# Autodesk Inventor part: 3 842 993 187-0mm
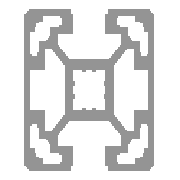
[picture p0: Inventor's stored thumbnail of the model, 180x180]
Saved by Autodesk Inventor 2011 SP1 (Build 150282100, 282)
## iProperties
Category: End -/-
Created: 2011-02
Part Number: 3 842 993 187-0mm
Document SubType Name: Modeling
Designer: SRW
Density: 2.71 g/cm^3
Categories: <MemberInstance><Categories><Category DisplayName="Structural Shapes" InternalName="089c4875-fa83-4c05-b084-43b9cc11f5ed" Mnemonic="GRDR"><CategoryParameter Dis
Stock Number: 3 842 993 187
Description: PROFILE 40x40 2S, -/-
Material: Aluminum-6061
Mass: 40.3687 g
Surface Area: 148.352 cm^2
Volume: 14.8962 cm^3
G_L: 25.000 mm
Author: SRW
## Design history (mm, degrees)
node "Blocks"
  sketch "40x40 2S"
    geometry: L1 (67.598, 49.273)-(67.598, 50.273); L2 (63.848, 46.523)-(64.848, 46.523); L3 (63.848, 44.273)-(63.848, 46.523); L4 (69.848, 53.273)-(64.848, 53.273); L5 (64.848, 53.273)-(64.848, 52.023); L6 (62.098, 49.273)-(60.848, 49.273); L7 (60.848, 49.273)-(60.848, 44.273); L8 (65.348, 39.773)-(60.848, 39.773); L9 (60.848, 39.773)-(60.848, 29.773); L10 (96.348, 54.773)-(85.148, 54.773); L11 (85.148, 53.273)-(84.348, 53.273); L12 (85.148, 54.773)-(85.148, 53.273); L13 (93.848, 53.273)-(88.848, 53.273); L14 (88.848, 50.273)-(91.098, 50.273); L15 (97.848, 49.273)-(96.598, 49.273); L16 (91.098, 50.273)-(91.098, 49.273); L17 (84.348, 53.273)-(84.348, 48.773); L18 (93.848, 46.523)-(94.848, 46.523); L19 (93.348, 45.023)-(91.012, 45.023); L20 (94.848, 46.523)-(94.848, 44.273); L21 (97.848, 44.273)-(97.848, 49.273); L22 (93.348, 39.773)-(93.348, 45.023); L23 (97.848, 39.773)-(93.348, 39.773); L24 (93.848, 52.023)-(93.848, 53.273); L25 (97.848, 20.273)-(97.848, 25.273); L26 (96.598, 20.273)-(97.848, 20.273); L27 (94.848, 25.273)-(94.848, 23.023); L28 (93.848, 16.273)-(93.848, 17.523); L29 (94.848, 23.023)-(93.848, 23.023); L30 (93.348, 24.523)-(93.348, 29.773); L31 (91.098, 20.273)-(91.098, 19.273); L32 (91.012, 24.523)-(93.348, 24.523); L33 (88.848, 16.273)-(93.848, 16.273); L34 (86.848, 28.687)-(91.012, 24.523); L35 (85.148, 14.773)-(96.348, 14.773); L36 (85.148, 16.273)-(85.148, 14.773); L37 (84.348, 20.773)-(84.348, 16.273); L38 (84.348, 16.273)-(85.148, 16.273); L39 (91.098, 19.273)-(88.848, 19.273); L40 (89.398, 20.773)-(84.348, 20.773); L41 (89.398, 23.309)-(89.398, 20.773); L42 (85.434, 27.273)-(89.398, 23.309); L43 (89.398, 46.237)-(85.434, 42.273); L44 (89.398, 48.773)-(89.398, 46.237); L45 (84.348, 48.773)-(89.398, 48.773); L46 (99.348, 17.773)-(99.348, 51.773); L47 (81.341, 30.188)-(81.608, 29.573); L48 (81.608, 39.973)-(81.341, 39.359); L49 (81.608, 29.573)-(84.548, 29.573); L50 (84.548, 39.973)-(81.608, 39.973); L51 (83.934, 36.766)-(84.548, 37.034); L52 (84.548, 32.513)-(83.934, 32.78); L53 (84.548, 37.034)-(84.548, 39.973); L54 (84.548, 29.573)-(84.548, 32.513); L55 (91.012, 45.023)-(86.848, 40.859); L56 (93.348, 29.773)-(97.848, 29.773); L57 (97.848, 29.773)-(97.848, 39.773); L58 (86.848, 40.859)-(86.848, 28.687); L59 (73.262, 27.273)-(85.434, 27.273); L60 (74.148, 32.513)-(74.148, 29.573); L61 (74.148, 39.973)-(74.148, 37.034); L62 (74.763, 32.78)-(74.148, 32.513); L63 (74.148, 37.034)-(74.763, 36.766); L64 (77.088, 39.973)-(74.148, 39.973)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; A1 r 2.75 centre (64.848, 49.273) between (64.848, 46.523) and (67.598, 49.273); A2 r 2.75 centre (64.848, 49.273) between (64.848, 52.023) and (62.098, 49.273); A3 r 1.5 centre (62.348, 44.273) between (60.848, 44.273) and (63.848, 44.273); A4 r 3 centre (96.348, 51.773) between (99.348, 51.773) and (96.348, 54.773); A5 r 1.5 centre (88.848, 51.773) between (88.848, 53.273) and (88.848, 50.273); A6 r 2.75 centre (93.848, 49.273) between (96.598, 49.273) and (93.848, 52.023); A7 r 2.75 centre (93.848, 49.273) between (91.098, 49.273) and (93.848, 46.523); A8 r 1.5 centre (96.348, 44.273) between (94.848, 44.273) and (97.848, 44.273); A9 r 3 centre (96.348, 17.773) between (96.348, 14.773) and (99.348, 17.773); A10 r 1.5 centre (96.348, 25.273) between (97.848, 25.273) and (94.848, 25.273); A11 r 2.75 centre (93.848, 20.273) between (93.848, 17.523) and (96.598, 20.273); A12 r 2.75 centre (93.848, 20.273) between (93.848, 23.023) and (91.098, 20.273); A13 r 1.5 centre (88.848, 17.773) between (88.848, 19.273) and (88.848, 16.273); A14 r 5 centre (79.348, 34.773) between (83.934, 32.78) and (83.934, 36.766); A15 r 5 centre (79.348, 34.773) between (74.763, 36.766) and (74.763, 32.78); A16 r 5 centre (79.348, 34.773) between (77.355, 30.188) and (81.341, 30.188); A17 r 5 centre (79.348, 34.773) between (81.341, 39.359) and (77.355, 39.359); A18 r 3 centre (62.348, 17.773) between (59.348, 17.773) and (62.348, 14.773); A19 r 1.5 centre (62.348, 25.273) between (63.848, 25.273) and (60.848, 25.273); A20 r 2.75 centre (64.848, 20.273) between (67.598, 20.273) and (64.848, 23.023); A21 r 1.5 centre (69.848, 17.773) between (69.848, 16.273) and (69.848, 19.273); A22 r 2.75 centre (64.848, 20.273) between (62.098, 20.273) and (64.848, 17.523); A23 r 3 centre (62.348, 51.773) between (62.348, 54.773) and (59.348, 51.773); A24 r 1.5 centre (69.848, 51.773) between (69.848, 50.273) and (69.848, 53.273); 1 further point
    constraints: 200 end point, 48 point on circle, 24 centre point, 1 coincident
node "Start Plane"
node "End Plane"
sketch "Sketch1"
  geometry: 1 further point
  constraints: 1 other
extrude "Body" new body sketch "Sketch1" stored distance "d4" = 0.13; taper "d5" = 0 deg
node "Driven Length"
  sketch "Sketch51"
    geometry: L1 (0, 0)-(10, 0) reference
    constraints: 2 end point, 1 horizontal
  workplane "Work Plane22"
  sketch "Sketch52"
    geometry: L1 (-28, 0)-(28, 0) reference; L2 (-28, 25)-(28, 25) reference
    dimensions: "d7" = 25 distance between parallel lines of L1 L2 (derived)
sketch "Sketch9"
  geometry: 1 further point
hole "M12/-" sketch "Sketch9" at (0, 0) diameter "d17" = 10.106; stored, may be unused: countersink angle "d21" = 90 deg, drill point angle "d23" = 118 deg; dims "d18" = 6, "d19" = 4, "d20" = 2, "d22" = 55
sketch "Sketch10"
  geometry: 1 further point
hole "-/M12" sketch "Sketch10" at (0, 0) diameter "d24" = 10.106; stored, may be unused: countersink angle "d28" = 90 deg, drill point angle "d30" = 118 deg; dims "d25" = 6, "d26" = 4, "d27" = 2, "d29" = 55
sketch "Sketch11"
  geometry: L1 (-13.7, 0)-(12.2, 0) reference; C1 r 8.5 at (0, 20); 1 further point
  constraints: 1 centre point, 1 vertical alignment
  dimensions: "d31" = 20 distance from line of C1.centre L1; "d32" = 17 diameter of C1
extrude "D17/-" cut sketch "Sketch11" stored distance "d33" = 10; taper "d34" = 0 deg
sketch "Sketch12"
  geometry: L1 (-13.7, 25)-(12.2, 25) reference; C1 r 8.5 at (0, 5); 1 further point
  constraints: 1 centre point, 1 vertical alignment
  dimensions: "d35" = 17 diameter of C1; "d36" = 20 distance from line of L1 C1.centre
extrude "-/D17" cut sketch "Sketch12" stored distance "d37" = 10; taper "d38" = 0 deg
sketch "Sketch13"
  geometry: L1 (-12.98, 0)-(7.88, 0) reference; C1 r 4.9 at (0, 20); 1 further point
  constraints: 1 centre point, 1 vertical alignment
  dimensions: "d39" = 9.8 diameter of C1; "d40" = 20 distance from line of C1.centre L1
extrude "D9.8/-" cut sketch "Sketch13" stored distance "d41" = 10; taper "d42" = 0 deg
sketch "Sketch14"
  geometry: L1 (-12.98, 25)-(7.88, 25) reference; C1 r 4.9 at (0, 5); 1 further point
  constraints: 1 centre point, 1 vertical alignment
  dimensions: "d43" = 9.8 diameter of C1; "d44" = 20 distance from line of L1 C1.centre
extrude "-/D9.8" cut sketch "Sketch14" stored distance "d45" = 10; taper "d46" = 0 deg
sketch "Sketch15"
  geometry: L1 (-6.86, 25)-(6.86, 25) reference; C1 r 4.9 at (0, 5); 1 further point
  constraints: 1 centre point, 1 vertical alignment
  dimensions: "d47" = 9.8 diameter of C1; "d48" = 20 distance from line of L1 C1.centre
extrude "-/D9.8VS" cut sketch "Sketch15" stored distance "d49" = 10; taper "d50" = 0 deg
sketch "Sketch26"
  geometry: L1 (-6.86, 0)-(6.86, 0) reference; C1 r 4.9 at (0, 20); 1 further point
  constraints: 1 centre point, 1 vertical alignment
  dimensions: "d62" = 9.8 diameter of C1; "d65" = 20 distance from line of L1 C1.centre
extrude "D9.8VS/-" cut sketch "Sketch26" stored distance "d63" = 10; taper "d64" = 0 deg
sketch "Sketch37"
  geometry: L1 (-11.9, 0)-(11.9, 0) reference; L2 (-11.9, 25)-(11.9, 25) reference; C1 r 8.5 at (0, 20); 1 further point
  constraints: 1 centre point, 1 vertical alignment
  dimensions: "d76" = 20 distance from line of C1.centre L1; "d77" = 17 diameter of C1
extrude "D17VS/-" cut sketch "Sketch37" stored distance "d78" = 10; taper "d79" = 0 deg
sketch "Sketch38"
  geometry: L1 (-11.9, 25)-(11.9, 25) reference; C1 r 8.5 at (0, 5); 1 further point
  constraints: 1 centre point, 1 vertical alignment
  dimensions: "d80" = 17 diameter of C1; "d81" = 20 distance from line of L1 C1.centre
extrude "-/D17VS" cut sketch "Sketch38" stored distance "d82" = 10; taper "d83" = 0 deg
body "Solid1"
node "40x40 2S:1"
other parameters: "Length" = 25, "G_OFFSET_START" = 0 [user parameter; used in 2 equation terms], "G_OFFSET_END" = 0 [user parameter; used in 2 equation terms], "d2" = 0 (computed from G_OFFSET_START), "d3" = 25 (= Length + G_OFFSET_END), "G_L" = 25 (= d7) [user parameter], "Length2" = 25 (= G_OFFSET_START + Length + G_OFFSET_END) [user parameter], "d96" = 90 deg
